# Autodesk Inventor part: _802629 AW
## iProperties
Shininess: 64.0
Length Units: 11269
Angle Units: 11279
Time Units: 11290
Mass Units: 11283
Length Display Precision: 3
Angle Display Precision: 2
Compacted: True
Part Number: _802629 AW
Document SubType Name: Modeling
Created: 2003-07
Material: Standard
Designer: achiml
Density: 0.0
Volumn: 0.0
Area: 0.0
PropertySet Name: Model Information
Control State: 0
Master: False
Checked Out: False
Author: achiml
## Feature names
1. Drehung2 [Revolution]
